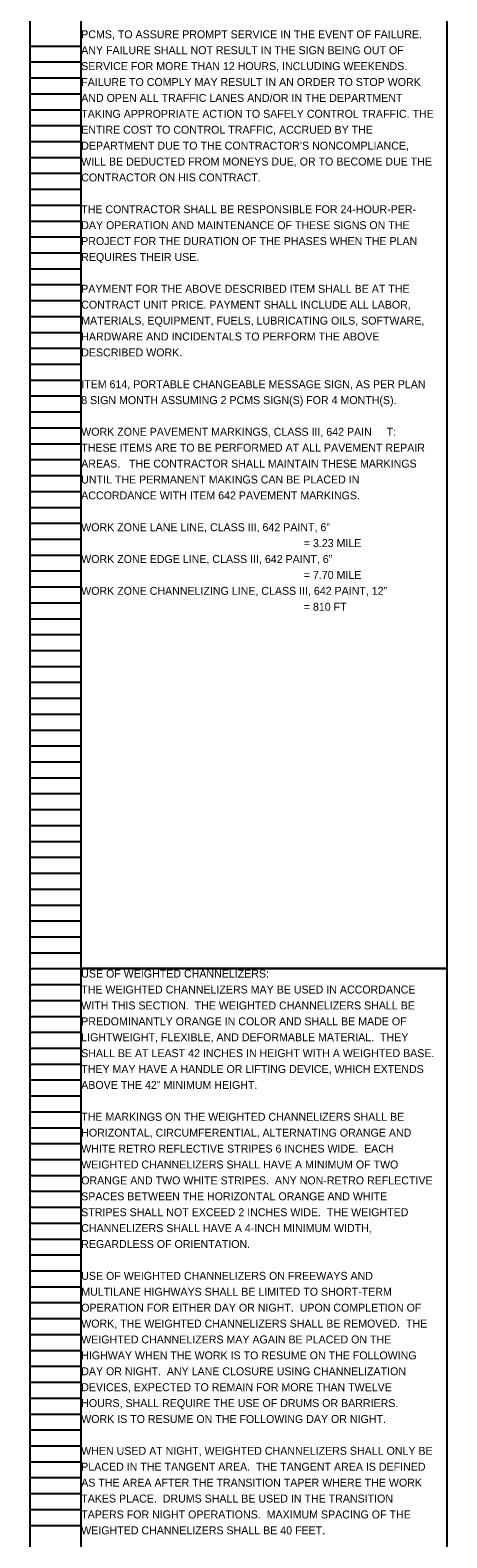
# Model space of a CAD drawing. Extents: x 16463 to 16500, y 5400 to 5823.
# Drawn here: x 16463.05 to 16470.39, y 5611.85 to 5638.39 of the extents above; entities that cross this region are included whole.
import ezdxf

# ---------------------------------------------------------------- set-up
doc = ezdxf.new("R2010")
doc.units = 0
for name, color, linetype in [('SC_Scratch1', 7, 'Continuous'), ('SH_Data', 7, 'Continuous'), ('SH_Text', 7, 'Continuous')]:
    doc.layers.add(name, color=color, linetype=linetype)

msp = doc.modelspace()

# ---------------------------------------------------------------- linework, layer by layer
at = {"layer": 'SC_Scratch1'}
for points in [[(16463.949, 5642.032), (16470.389, 5642.032), (16470.389, 5621.872), (16463.949, 5621.872)], [(16463.949, 5621.872), (16470.389, 5621.872), (16470.389, 5601.712), (16463.949, 5601.712)]]:
    msp.add_lwpolyline(points, close=True, dxfattribs=at)
at = {"layer": 'SH_Data'}
for p, q in [((16463.049, 5621.872), (16463.049, 5642.032)), ((16463.949, 5621.872), (16463.949, 5642.032)), ((16463.049, 5638.112), (16463.949, 5638.112)), ((16463.049, 5637.832), (16463.949, 5637.832)), ((16463.049, 5637.552), (16463.949, 5637.552)), ((16463.049, 5637.272), (16463.949, 5637.272)), ((16463.049, 5636.992), (16463.949, 5636.992)), ((16463.049, 5636.712), (16463.949, 5636.712)), ((16463.049, 5636.432), (16463.949, 5636.432)), ((16463.049, 5636.152), (16463.949, 5636.152)), ((16463.049, 5635.872), (16463.949, 5635.872)), ((16463.049, 5635.592), (16463.949, 5635.592)), ((16463.049, 5635.312), (16463.949, 5635.312)), ((16463.049, 5635.032), (16463.949, 5635.032)), ((16463.049, 5634.752), (16463.949, 5634.752)), ((16463.049, 5634.472), (16463.949, 5634.472)), ((16463.049, 5634.192), (16463.949, 5634.192)), ((16463.049, 5633.912), (16463.949, 5633.912)), ((16463.049, 5633.632), (16463.949, 5633.632)), ((16463.049, 5633.352), (16463.949, 5633.352)), ((16463.049, 5633.072), (16463.949, 5633.072)), ((16463.049, 5632.792), (16463.949, 5632.792)), ((16463.049, 5632.512), (16463.949, 5632.512)), ((16463.049, 5632.232), (16463.949, 5632.232)), ((16463.049, 5631.952), (16463.949, 5631.952)), ((16463.049, 5631.672), (16463.949, 5631.672)), ((16463.049, 5631.392), (16463.949, 5631.392)), ((16463.049, 5631.112), (16463.949, 5631.112)), ((16463.049, 5630.832), (16463.949, 5630.832)), ((16463.049, 5630.552), (16463.949, 5630.552)), ((16463.049, 5630.272), (16463.949, 5630.272)), ((16463.049, 5629.992), (16463.949, 5629.992)), ((16463.049, 5629.712), (16463.949, 5629.712)), ((16463.049, 5629.432), (16463.949, 5629.432)), ((16463.049, 5629.152), (16463.949, 5629.152)), ((16463.049, 5628.872), (16463.949, 5628.872)), ((16463.049, 5628.592), (16463.949, 5628.592)), ((16463.049, 5628.312), (16463.949, 5628.312)), ((16463.049, 5628.032), (16463.949, 5628.032)), ((16463.049, 5627.752), (16463.949, 5627.752)), ((16463.049, 5627.472), (16463.949, 5627.472)), ((16463.049, 5627.192), (16463.949, 5627.192)), ((16463.049, 5626.912), (16463.949, 5626.912)), ((16463.049, 5626.632), (16463.949, 5626.632)), ((16463.049, 5626.352), (16463.949, 5626.352)), ((16463.049, 5626.072), (16463.949, 5626.072)), ((16463.049, 5625.792), (16463.949, 5625.792)), ((16463.049, 5625.512), (16463.949, 5625.512)), ((16463.049, 5625.232), (16463.949, 5625.232)), ((16463.049, 5624.952), (16463.949, 5624.952)), ((16463.049, 5624.672), (16463.949, 5624.672)), ((16463.049, 5624.392), (16463.949, 5624.392)), ((16463.049, 5624.112), (16463.949, 5624.112)), ((16463.049, 5623.832), (16463.949, 5623.832)), ((16463.049, 5623.552), (16463.949, 5623.552)), ((16463.049, 5623.272), (16463.949, 5623.272)), ((16463.049, 5622.992), (16463.949, 5622.992)), ((16463.049, 5622.712), (16463.949, 5622.712)), ((16463.049, 5622.432), (16463.949, 5622.432)), ((16463.049, 5622.152), (16463.949, 5622.152)), ((16463.049, 5601.712), (16463.049, 5621.872)), ((16463.049, 5621.872), (16463.949, 5621.872)), ((16463.049, 5621.872), (16463.949, 5621.872)), ((16463.949, 5601.712), (16463.949, 5621.872)), ((16463.049, 5621.592), (16463.949, 5621.592)), ((16463.049, 5621.312), (16463.949, 5621.312)), ((16463.049, 5621.032), (16463.949, 5621.032)), ((16463.049, 5620.752), (16463.949, 5620.752)), ((16463.049, 5620.472), (16463.949, 5620.472)), ((16463.049, 5620.192), (16463.949, 5620.192)), ((16463.049, 5619.912), (16463.949, 5619.912)), ((16463.049, 5619.632), (16463.949, 5619.632)), ((16463.049, 5619.352), (16463.949, 5619.352)), ((16463.049, 5619.072), (16463.949, 5619.072)), ((16463.049, 5618.792), (16463.949, 5618.792)), ((16463.049, 5618.512), (16463.949, 5618.512)), ((16463.049, 5618.232), (16463.949, 5618.232)), ((16463.049, 5617.952), (16463.949, 5617.952)), ((16463.049, 5617.672), (16463.949, 5617.672)), ((16463.049, 5617.392), (16463.949, 5617.392)), ((16463.049, 5617.112), (16463.949, 5617.112)), ((16463.049, 5616.832), (16463.949, 5616.832)), ((16463.049, 5616.552), (16463.949, 5616.552)), ((16463.049, 5616.272), (16463.949, 5616.272)), ((16463.049, 5615.992), (16463.949, 5615.992)), ((16463.049, 5615.712), (16463.949, 5615.712)), ((16463.049, 5615.432), (16463.949, 5615.432)), ((16463.049, 5615.152), (16463.949, 5615.152)), ((16463.049, 5614.872), (16463.949, 5614.872)), ((16463.049, 5614.592), (16463.949, 5614.592)), ((16463.049, 5614.312), (16463.949, 5614.312)), ((16463.049, 5614.032), (16463.949, 5614.032)), ((16463.049, 5613.752), (16463.949, 5613.752)), ((16463.049, 5613.472), (16463.949, 5613.472)), ((16463.049, 5613.192), (16463.949, 5613.192)), ((16463.049, 5612.912), (16463.949, 5612.912)), ((16463.049, 5612.632), (16463.949, 5612.632)), ((16463.049, 5612.352), (16463.949, 5612.352)), ((16463.049, 5612.072), (16463.949, 5612.072))]:
    msp.add_line(p, q, dxfattribs=at)

# ---------------------------------------------------------------- texts
at = {"layer": 'SH_Text'}
for s, p in [('PCMS, TO ASSURE PROMPT SERVICE IN THE EVENT OF FAILURE. ', (16463.949, 5638.249)), ('ANY FAILURE SHALL NOT RESULT IN THE SIGN BEING OUT OF ', (16463.949, 5637.969)), ('SERVICE FOR MORE THAN 12 HOURS, INCLUDING WEEKENDS. ', (16463.949, 5637.689)), ('FAILURE TO COMPLY MAY RESULT IN AN ORDER TO STOP WORK ', (16463.949, 5637.409)), ('AND OPEN ALL TRAFFIC LANES AND/OR IN THE DEPARTMENT ', (16463.949, 5637.129)), ('TAKING APPROPRIATE ACTION TO SAFELY CONTROL TRAFFIC. THE ', (16463.949, 5636.849)), ('ENTIRE COST TO CONTROL TRAFFIC, ACCRUED BY THE ', (16463.949, 5636.569)), ('DEPARTMENT DUE TO THE CONTRACTOR’S NONCOMPLIANCE, ', (16463.949, 5636.289)), ('WILL BE DEDUCTED FROM MONEYS DUE, OR TO BECOME DUE THE ', (16463.949, 5636.009)), ('CONTRACTOR ON HIS CONTRACT.', (16463.949, 5635.729)), ('THE CONTRACTOR SHALL BE RESPONSIBLE FOR 24-HOUR-PER-', (16463.949, 5635.169)), ('DAY OPERATION AND MAINTENANCE OF THESE SIGNS ON THE ', (16463.949, 5634.889)), ('PROJECT FOR THE DURATION OF THE PHASES WHEN THE PLAN ', (16463.949, 5634.609)), ('REQUIRES THEIR USE. ', (16463.949, 5634.329)), ('PAYMENT FOR THE ABOVE DESCRIBED ITEM SHALL BE AT THE ', (16463.949, 5633.769)), ('CONTRACT UNIT PRICE. PAYMENT SHALL INCLUDE ALL LABOR, ', (16463.949, 5633.489)), ('MATERIALS, EQUIPMENT, FUELS, LUBRICATING OILS, SOFTWARE, ', (16463.949, 5633.209)), ('HARDWARE AND INCIDENTALS TO PERFORM THE ABOVE ', (16463.949, 5632.929)), ('DESCRIBED WORK. ', (16463.949, 5632.649)), ('ITEM 614, PORTABLE CHANGEABLE MESSAGE SIGN, AS PER PLAN ', (16463.949, 5632.089)), ('8 SIGN MONTH ASSUMING 2 PCMS SIGN(S) FOR 4 MONTH(S).', (16463.949, 5631.809)), ('WORK ZONE PAVEMENT MARKINGS, CLASS III, 642 PAIN', (16463.949, 5631.252)), ('T:', (16469.329, 5631.252)), ('THESE ITEMS ARE TO BE PERFORMED AT ALL PAVEMENT REPAIR ', (16463.949, 5630.972)), ('AREAS.   THE CONTRACTOR SHALL MAINTAIN THESE MARKINGS ', (16463.949, 5630.692)), ('UNTIL THE PERMANENT MAKINGS CAN BE PLACED IN ', (16463.949, 5630.412)), ('ACCORDANCE WITH ITEM 642 PAVEMENT MARKINGS. ', (16463.949, 5630.132)), ('WORK ZONE LANE LINE, CLASS III, 642 PAINT, 6”         ', (16463.949, 5629.572)), ('= 3.23 MILE', (16467.869, 5629.292)), ('WORK ZONE EDGE LINE, CLASS III, 642 PAINT, 6”', (16463.949, 5629.012)), ('= 7.70 MILE', (16467.869, 5628.732)), ('WORK ZONE CHANNELIZING LINE, CLASS III, 642 PAINT, 12”  ', (16463.949, 5628.452)), ('= 810 FT', (16467.869, 5628.172)), ('USE OF WEIGHTED CHANNELIZERS:', (16463.949, 5621.714)), ('THE WEIGHTED CHANNELIZERS MAY BE USED IN ACCORDANCE ', (16463.949, 5621.434)), ('WITH THIS SECTION.  THE WEIGHTED CHANNELIZERS SHALL BE ', (16463.949, 5621.154)), ('PREDOMINANTLY ORANGE IN COLOR AND SHALL BE MADE OF ', (16463.949, 5620.874)), ('LIGHTWEIGHT, FLEXIBLE, AND DEFORMABLE MATERIAL.  THEY ', (16463.949, 5620.594)), ('SHALL BE AT LEAST 42 INCHES IN HEIGHT WITH A WEIGHTED BASE.  ', (16463.949, 5620.314)), ('THEY MAY HAVE A HANDLE OR LIFTING DEVICE, WHICH EXTENDS ', (16463.949, 5620.034)), ('ABOVE THE 42" MINIMUM HEIGHT.', (16463.949, 5619.754)), ('THE MARKINGS ON THE WEIGHTED CHANNELIZERS SHALL BE ', (16463.949, 5619.194)), ('HORIZONTAL, CIRCUMFERENTIAL, ALTERNATING ORANGE AND ', (16463.949, 5618.914)), ('WHITE RETRO REFLECTIVE STRIPES 6 INCHES WIDE.  EACH ', (16463.949, 5618.634)), ('WEIGHTED CHANNELIZERS SHALL HAVE A MINIMUM OF TWO ', (16463.949, 5618.354)), ('ORANGE AND TWO WHITE STRIPES.  ANY NON-RETRO REFLECTIVE ', (16463.949, 5618.074)), ('SPACES BETWEEN THE HORIZONTAL ORANGE AND WHITE ', (16463.949, 5617.794)), ('STRIPES SHALL NOT EXCEED 2 INCHES WIDE.  THE WEIGHTED ', (16463.949, 5617.514)), ('CHANNELIZERS SHALL HAVE A 4-INCH MINIMUM WIDTH, ', (16463.949, 5617.234)), ('REGARDLESS OF ORIENTATION.', (16463.949, 5616.954)), ('USE OF WEIGHTED CHANNELIZERS ON FREEWAYS AND ', (16463.949, 5616.394)), ('MULTILANE HIGHWAYS SHALL BE LIMITED TO SHORT-TERM ', (16463.949, 5616.114)), ('OPERATION FOR EITHER DAY OR NIGHT.  UPON COMPLETION OF ', (16463.949, 5615.834)), ('WORK, THE WEIGHTED CHANNELIZERS SHALL BE REMOVED.  THE ', (16463.949, 5615.554)), ('WEIGHTED CHANNELIZERS MAY AGAIN BE PLACED ON THE ', (16463.949, 5615.274)), ('HIGHWAY WHEN THE WORK IS TO RESUME ON THE FOLLOWING ', (16463.949, 5614.994)), ('DAY OR NIGHT.  ANY LANE CLOSURE USING CHANNELIZATION ', (16463.949, 5614.714)), ('DEVICES, EXPECTED TO REMAIN FOR MORE THAN TWELVE ', (16463.949, 5614.434)), ('HOURS, SHALL REQUIRE THE USE OF DRUMS OR BARRIERS.  ', (16463.949, 5614.154)), ('WORK IS TO RESUME ON THE FOLLOWING DAY OR NIGHT.', (16463.949, 5613.874)), ('WHEN USED AT NIGHT, WEIGHTED CHANNELIZERS SHALL ONLY BE ', (16463.949, 5613.314)), ('PLACED IN THE TANGENT AREA.  THE TANGENT AREA IS DEFINED ', (16463.949, 5613.034)), ('AS THE AREA AFTER THE TRANSITION TAPER WHERE THE WORK ', (16463.949, 5612.754)), ('TAKES PLACE.  DRUMS SHALL BE USED IN THE TRANSITION ', (16463.949, 5612.474)), ('TAPERS FOR NIGHT OPERATIONS.  MAXIMUM SPACING OF THE ', (16463.949, 5612.194)), ('WEIGHTED CHANNELIZERS SHALL BE 40 FEET.', (16463.949, 5611.914))]:
    msp.add_text(s, height=0.14, dxfattribs=at).set_placement(p)

doc.saveas('drawing.dxf')
